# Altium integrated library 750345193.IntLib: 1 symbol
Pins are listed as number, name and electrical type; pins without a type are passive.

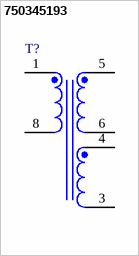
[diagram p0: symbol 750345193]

## 750345193
designator T?
Manufacturer Part Number: 750345193
footprint 750345193 (Footprint not found)
pins: 1, 3, 4, 5, 6, 8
